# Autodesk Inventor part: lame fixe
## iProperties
Shininess: 20.0
Angle Display Precision: 2
Document Length Units: 11269
Document Angle Units: 11279
Document Time Units: 11290
Document Mass Units: 11283
Document Length Units Precision: 3
Document Angle Units Precision: 2
Compacted: True
Created: 2002-04
Part Number: lame fixe
Material: Par défaut
Document SubType Name: Modélisation
Designer: thchene
Density: 0.0
Volumn: 0.0
Area: 0.0
PropertySet Name: Model Information
Control State: 0
Master: False
Checked Out: False
Author: thchene
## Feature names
1. Extrusion1
2. Extrusion2
3. Congé1 [Fillet]
4. Congé2 [Fillet]
5. Extrusion3
6. Congé3 [Fillet]
7. Perçage1 [Hole]
8. Perçage2 [Hole]
9. Extrusion4
